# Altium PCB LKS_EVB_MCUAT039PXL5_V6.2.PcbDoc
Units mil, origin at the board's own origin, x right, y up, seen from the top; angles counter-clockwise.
Board outline 1544.1 x 1580 mil, 2 copper layers (Top Layer, Bottom Layer); 72 components, 49 nets, 196 pads, 133 vias.
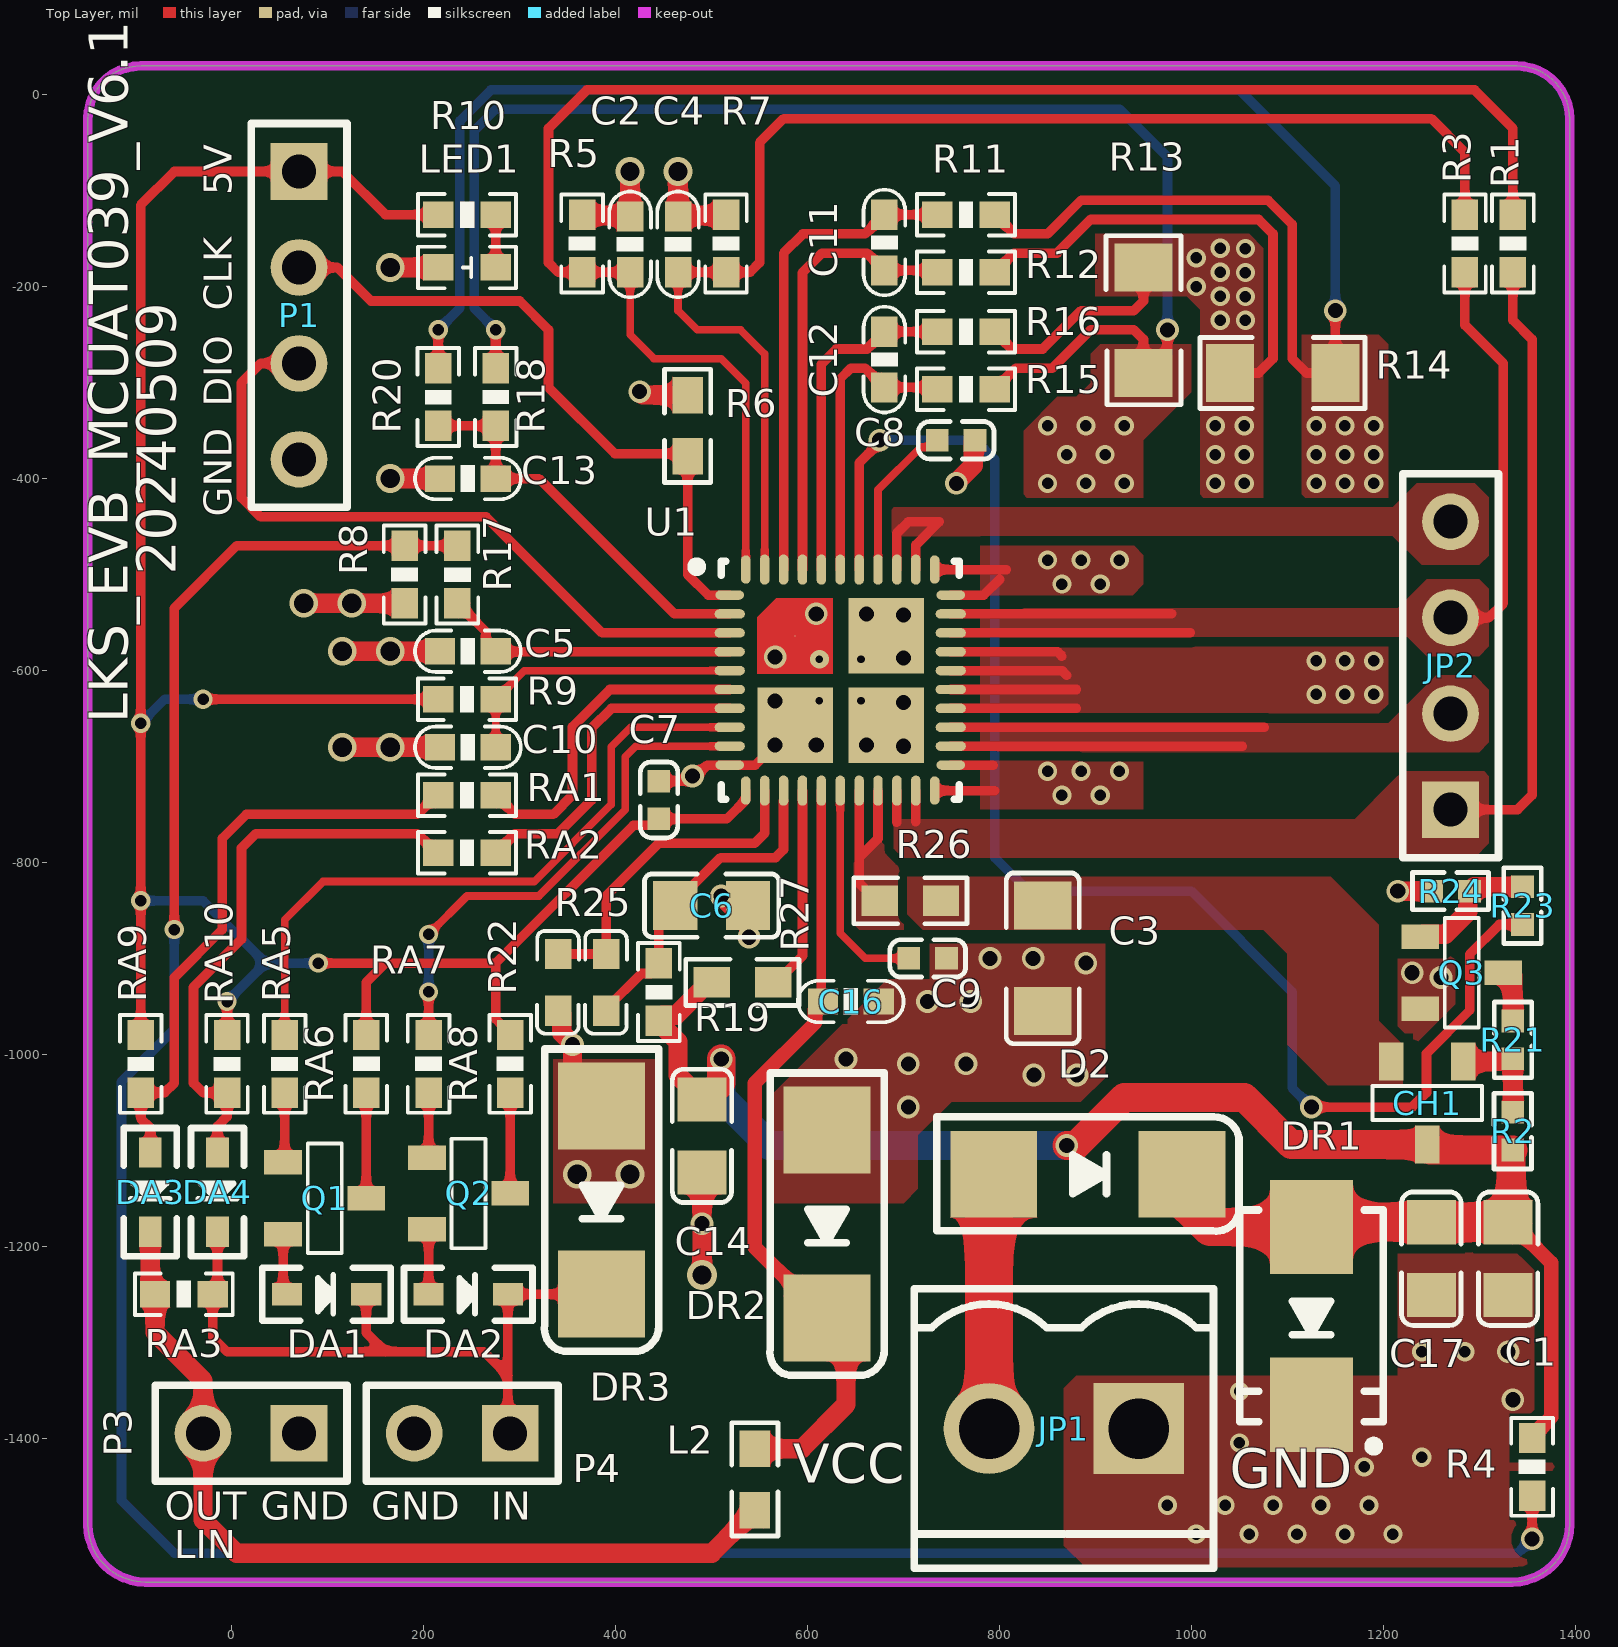
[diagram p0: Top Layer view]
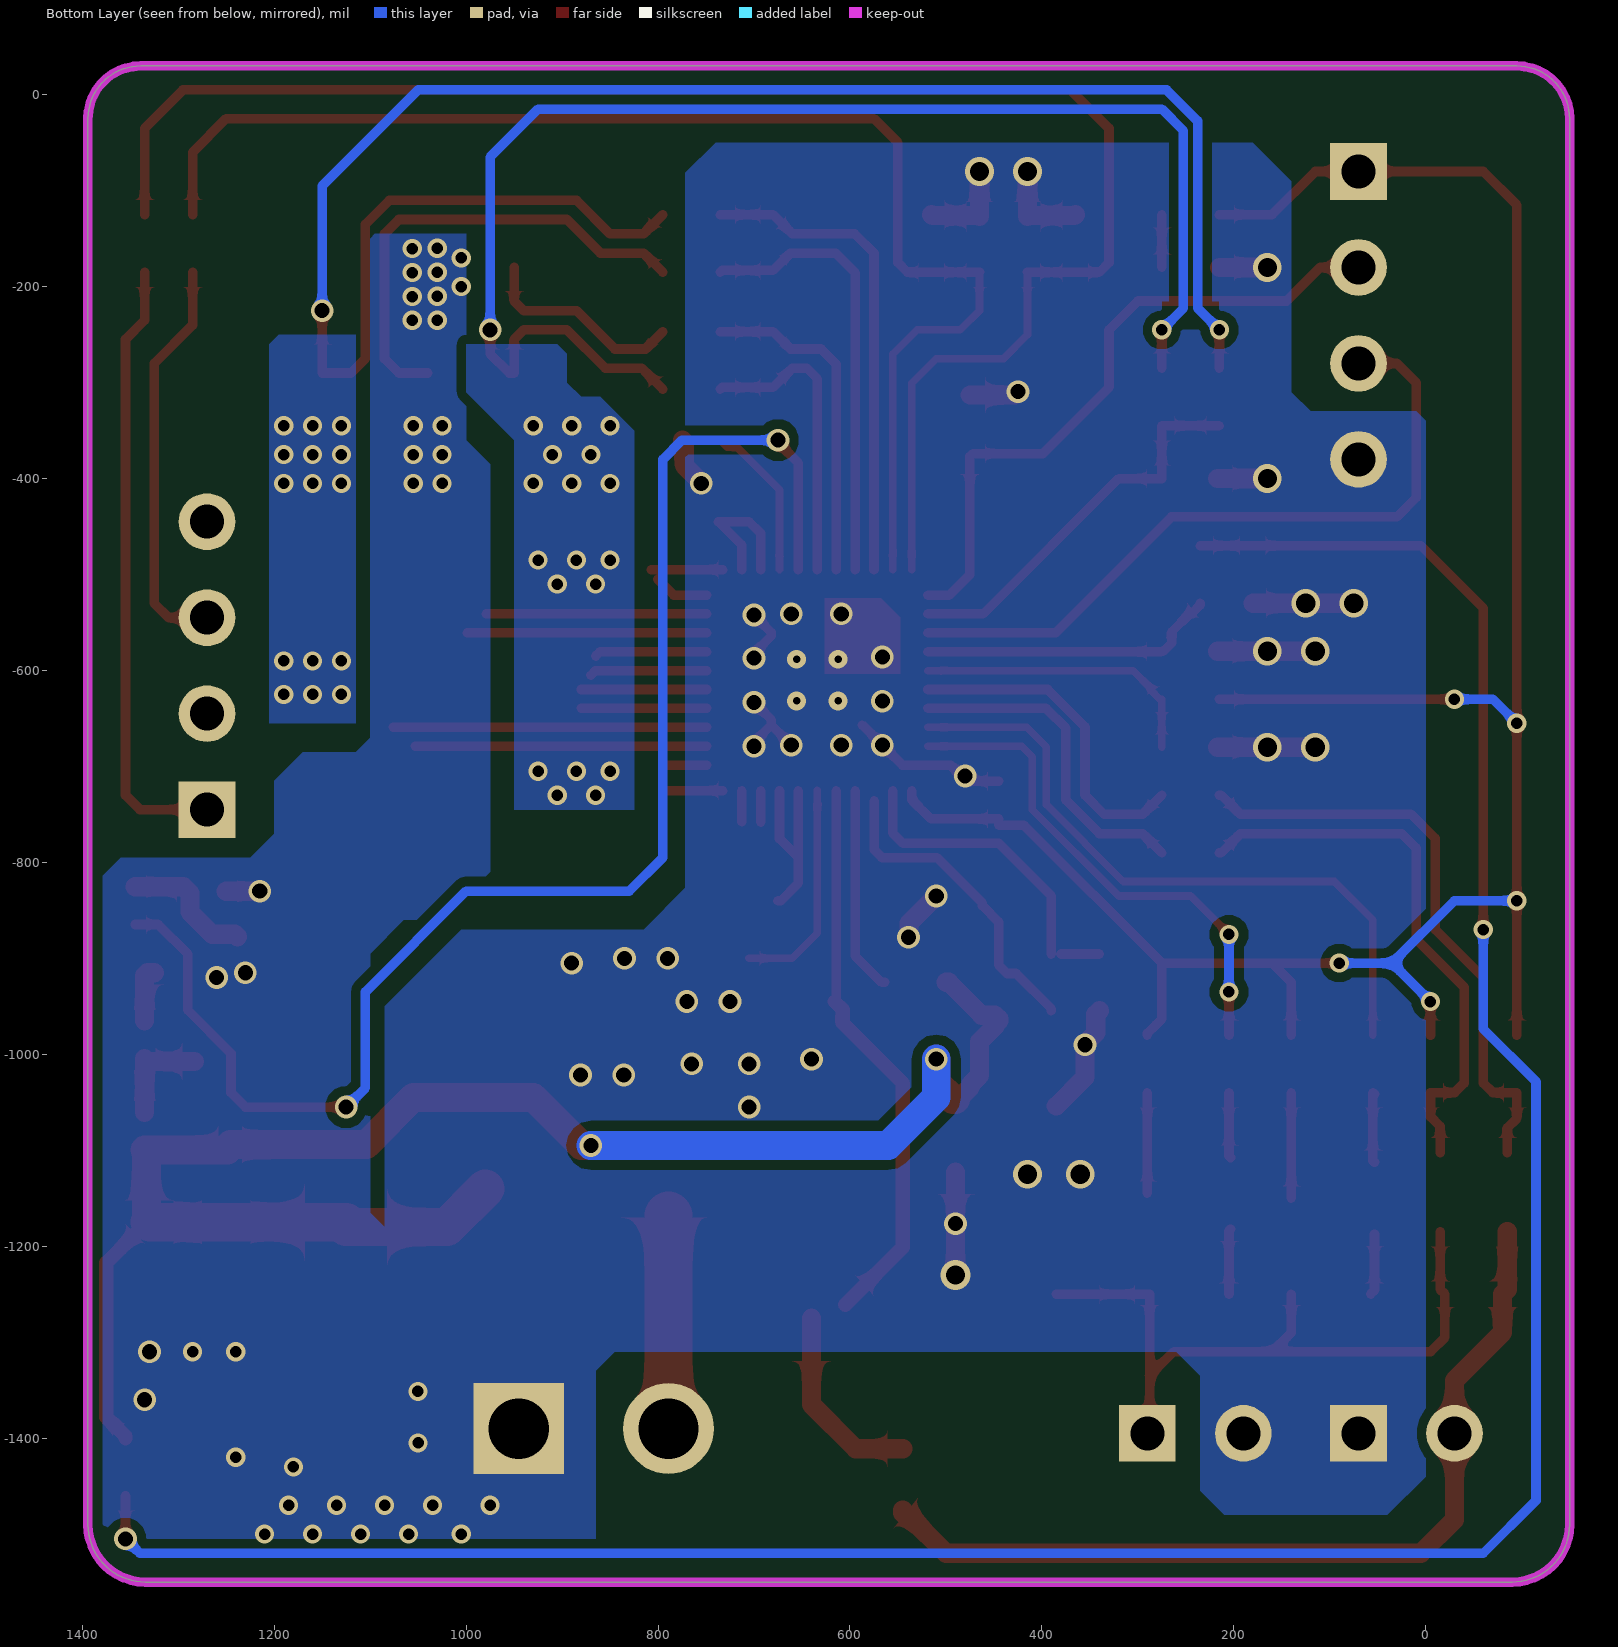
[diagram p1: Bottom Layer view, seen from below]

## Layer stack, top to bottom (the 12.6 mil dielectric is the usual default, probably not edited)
Top Solder: solder mask 0.4, Solder Resist, Dk 3.5
Top Layer: signal copper 1.4
Dielectric1: dielectric 12.6, FR-4, Dk 4.8
Bottom Layer: signal copper 1.4
Bottom Solder: solder mask 0.4, Solder Resist, Dk 3.5

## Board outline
-150,-1490 -150,-25 cw(c-95,-25) -95,30 1339.1,30 cw(c1339.1,-25) 1394.1,-25 1394.1,-1490 cw(c1334.1,-1490) 1334.1,-1550 -90,-1550 cw(c-90,-1490)

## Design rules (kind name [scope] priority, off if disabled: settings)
Clearance Clearance_1 [InPolygon] p1: gap=10 ignorepadtopadclearanceinfootprint=FALSE
Clearance [All] p2: gap=5 ignorepadtopadclearanceinfootprint=FALSE
ComponentClearance [All] p1: gap=0 collisioncheckmode=3 verticalgap=0 showdistances=FALSE
FabricationTestpoint [(IsPad And (OnTopLayer Or OnBottomLayer))] p1: side=3 testpointundercomponent=TRUE minsize=40 maxsize=100 preferedsize=60 minholesize=0 maxholesize=40 preferedholesize=32 testpointgrid=1 allowsidetop=TRUE allowsidebottom=TRUE usegrid=TRUE gridtolerance=0.01
HoleSize [All] p1: absolutevalues=TRUE maxlimit=100 minlimit=0 maxpercent=80.000 minpercent=20.000
PolygonConnect [All] p1: connectstyle=Direct reliefconductorwidth=30 reliefentries=4 polygonreliefangle="90 Angle" airgapwidth=10
RoutingVias [All] p1: holewidth=12 width=20 viastyle="Through Hole" minholewidth=0 minwidth=10 maxholewidth=100 maxwidth=200
SilkToSolderMaskClearance SilkscreenOverComponentPads [IsPad] p1: minsilkscreentomaskgap=10 clearancetoexposedcopper=TRUE
SolderMaskExpansion [All] p1: expansion=4 istentingtop=FALSE
Width [All] p1: maxlimit=100 minlimit=7.87 preferedwidth=10
26 further rules are at their usual default settings.

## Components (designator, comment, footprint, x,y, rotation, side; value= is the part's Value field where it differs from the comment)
C1 "100nF/50V" 0805C 1330,-1213 r270 top
C2 "1nF/50V" 0603C 415,-156 r90 top
C3 "CL31A226KAHNNNE" 1206C 845,-900 r270 top
C4 "1nF/50V" 0603C 465,-156 r90 top
C5 "100nF/50V" 0603C 246,-580 r180 top
C6 "2.2uF/50V" 0805C 500,-845 r0 top
C7 "CL05A105KO5NNNC" 0402C 445,-735 r90 top
C8 "CL05A105KO5NNNC" 0402C 754.68,-360 r0 top
C9 "CL05A105KO5NNNC" 0402C 725,-900 r0 top
C10 "100nF/50V" 0603C 246,-680 r180 top
C11 "100pF/50V" 0603C 680,-154 r270 top
C12 "100pF/50V" 0603C 680,-276 r90 top
C13 "1nF/50V" 0603C 246,-400 r180 top
C14 "10uF/50V" 0805C 490,-1085 r270 top
C16 "100pF/50V" 0603C 645,-945 r0 top
C17 "10uF/50V" 0805C 1250,-1213 r270 top
CH1 "PMV250EPEAR" SOT-23#1 1285,-1015 r180 top
D2 "SSL310" SMA 794,-1125 r0 top
DA1 "1N4007" SOD-323 98.66,-1250 r0 top
DA2 "1N4007" SOD-323 246.34,-1250 r0 top
DA3 "1N4007" SOD-323 -85,-1143.66 r270 top
DA4 "1N4007" SOD-323 -15,-1143.66 r270 top
DR1 "SMBJ33CA" SMB 1125,-1272.52 r270 top
DR2 "SMAJ48A" SMA 620,-1079 r270 top
DR3 "SMAJ48A" SMA 385,-1054 r270 top
JP1 "B2P-VH(LF)(SN)" HT3.96-LI-2P 867.05,-1390 r180 top
JP2 "HDR-1X4" "HDR 1X4" 1270,-745 r90 top
L2 "120R@100Mhz" 0603R#1 545,-1443 r90 top value=K
LED1 "LED" "LED 0603G" 245,-180 r180 top
P1 "HDR-1X4" "HDR 1X4" 70,-80 r270 top
P3 "1X2" "HDR 1X2" 70,-1395 r180 top
P4 "1X2" "HDR 1X2" 290,-1395 r180 top
Q1 "S8050" SOT-23#2 96.69,-1150 r270 top
Q2 "S8050" SOT-23#2 246.69,-1145 r270 top
Q3 "SS8050" SOT-23#1 1245.87,-875.83 r270 top
R1 "10K  1%" 0603R#2 1335,-155 r90 top value=K
R2 "51K 5%" 0402R 1335,-1080 r270 top value=K
R3 "10K  1%" 0603R#2 1285,-155 r90 top value=K
R4 "510K  1%" 0603R#2 1355,-1430 r270 top value=K
R5 "1K 1%" 0603R#2 365,-155 r90 top value=K
R6 "1K" 0603R#1 475,-345 r270 top value=K
R7 "1K 1%" 0603R#2 515,-155 r90 top value=K
R8 "30K 1%" 0603R#2 180,-500 r90 top value=K
R9 "20K" 0603R#2 245,-630 r0 top value=K
R10 "3.3K" 0603R#2 245,-125 r180 top value=330
R11 "1K 1%" 0603R#2 765,-125 r180 top value=K
R12 "1K 1%" 0603R#2 765,-185 r180 top value=K
R13 "100mR 1%" 1206R 950,-235 r270 top value=K
R14 "100mR 1%" 1206R 1095,-290 r0 top value=K
R15 "1K 1%" 0603R#2 765,-306.95 r180 top value=K
R16 "1K 1%" 0603R#2 765,-246.95 r180 top value=K
R17 "1K" 0603R#2 235,-500 r90 top value=K
R18 "2K 1%" 0603R#2 275,-315 r90 top value=K
R19 "51R" 0603R#2 445,-935 r90 top value=K
R20 "2K 1%" 0603R#2 215,-315 r90 top value=K
R21 "4.7K 5%" 0402R 1335,-985 r90 top value=K
R22 "10K" "0603C _1" 340,-925 r270 top value=K
R23 "1K 5%" 0402R 1345,-845 r270 top value=K
R24 "10K 5%" 0402R 1270,-830 r180 top value=K
R25 "NC" "0603C _1" 390,-925 r270 top value=K
R26 "0R" 0603R#1 707,-840 r0 top value=K
R27 "0R" 0603R#1 532,-925 r0 top value=K
RA1 "5K" 0603R#2 245,-730 r180 top
RA2 "5K" 0603R#2 245,-790 r180 top
RA3 "1.5R" 0603R#2 -50,-1250 r0 top
RA5 "10K" 0603R#2 55,-1010 r90 top
RA6 "3.9K" 0603R#2 140,-1010 r270 top
RA7 "10K" 0603R#2 205,-1010 r90 top
RA8 "1.3K" 0603R#2 290,-1010 r270 top
RA9 "100K" 0603R#2 -95,-1010 r90 top
RA10 "100K" 0603R#2 -5,-1010 r90 top
U1 "LKS32AT039PXL5G6Q9" QFN42-AT039PXL5 634,-610 r0 top

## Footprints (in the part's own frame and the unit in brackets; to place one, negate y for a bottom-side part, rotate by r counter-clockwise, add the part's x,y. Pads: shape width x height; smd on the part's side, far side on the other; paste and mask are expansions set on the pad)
0402C [mm]
  rect 0.6x0.6 smd: 1(-0.5,0) 2(0.5,0)
  silkscreen extent -1,-0.5 1,0.49, body extent -0.5,-0.25 0.5,0.25, height 0.35
0402R [mm]
  rect 0.6x0.6 smd: 1(-0.5,0) 2(0.5,0)
  silkscreen extent -1,-0.5 1,0.49, body extent -0.5,-0.25 0.5,0.25, height 0.35
0603C [mm] "电容"
  rect 0.8x0.7 smd: 1(-0.737,0) 2(0.738,0)
  silkscreen extent -1.4,-0.55 1.4,0.55, body extent -0.8,-0.41 0.8,0.41, height 0.81
"0603C _1" [mm]
  rect 0.8x0.7 smd: 1(-0.75,0) 2(0.75,0)
  silkscreen extent -1.36,-0.56 1.36,0.55, body extent -0.8,-0.41 0.8,0.41, height 0.81
0603R#1 [mil]
  rect 38x32 smd: 1(-32,0) 2(32,0)
  silkscreen extent -59,-24 59,24, body extent -31,-16 32,16, height 16
0603R#2 [mil] "电阻"
  rect 31.5x27.56 smd: 1(-30,0) 2(30,0)
  silkscreen extent -51,-22 51,22, body extent -31,-16 32,16, height 18
0805C [mil] "电容"
  rect 46x51.18 smd: 1(-38,0) 2(38,0)
  silkscreen extent -69,-31 70,31, body extent -39,-24 39,24, height 20
1206C [mil]
  rect 50x60 smd: 1(-55,0) 2(55,0)
  silkscreen extent -89,-38 89,38, body extent -61,-31 65,32, height 24
1206R [mil]
  rect 50x60 smd: 1(-55,0) 2(55,0)
  silkscreen extent -88,-39 88,39, body extent -62,-31 64,32, height 24
"HDR 1X2" [mm] "单排针 2.54mm"
  rect 1.5x1.5 hole 0.9: 1(0,0)
  round 1.5 hole 0.9: 2(2.54,0)
  silkscreen extent -1.27,-1.27 3.81,1.27, body extent -1.27,-1.27 3.81,1.27, height 8.5
"HDR 1X4" [mm] "单排针 2.54mm"
  rect 1.5x1.5 hole 0.9: 1(0,0)
  round 1.5 hole 0.9: 2(2.54,0) 3(5.08,0) 4(7.62,0)
  silkscreen extent -1.27,-1.27 8.89,1.27, body extent -1.27,-1.27 8.89,1.27, height 8.5
HT3.96-LI-2P [mm] "HT3.96立插端子"
  rect 2.4x2.4 hole 1.6: 1(-1.98,0)
  round 2.4 hole 1.6: 2(1.98,0)
  silkscreen extent -3.96,-3.7 3.96,3.7, body extent -3.98,-3.7 3.98,3.7, height 10.05
"LED 0603G" [mm] "LED"
  rect 0.8x0.7 smd: 1(-0.762,0) 2(0.762,0)
  silkscreen extent -1.3,-0.55 1.3,0.55, body extent -0.8,-0.4 0.8,0.4, height 0.47
QFN42-AT039PXL5 [mm] "QFN, 42-Leads, Body 6.00x6.00mm, Pitch 0.50mm, Thermal Pad 2.00x2.00mm, IPC Medium Density"
  rect 2x2 smd: 0(-1.194,-1.194) 0(1.219,-1.194) 0(1.219,1.168)
  round 0.025 smd: 0(-1.194,1.168)
  oval 0.75x0.25 smd: 1(-2.925,2.25) 10(-2.925,-2.25) 22(2.925,-2.25) 31(2.925,2.25)
  oval 0.8x0.25 smd: 2(-2.925,1.75) 3(-2.925,1.25) 4(-2.925,0.75) 5(-2.925,0.25) 6(-2.925,-0.25) 7(-2.925,-0.75) 8(-2.925,-1.25) 9(-2.925,-1.75) 23(2.925,-1.75) 24(2.925,-1.25) 25(2.925,-0.75) 26(2.925,-0.25) 27(2.925,0.25) 28(2.925,0.75) 29(2.925,1.25) 30(2.925,1.75)
  oval 0.25x0.75 smd: 11(-2.5,-2.925) 21(2.5,-2.925) 32(2.5,2.925) 42(-2.5,2.925)
  oval 0.25x0.8 smd: 12(-2,-2.925) 13(-1.5,-2.925) 14(-1,-2.925) 15(-0.5,-2.925) 16(0,-2.925) 17(0.5,-2.925) 18(1,-2.925) 19(1.5,-2.925) 20(2,-2.925) 33(2,2.925) 34(1.5,2.925) 35(1,2.925) 36(0.5,2.925) 37(0,2.925) 38(-0.5,2.925) 39(-1,2.925) 40(-1.5,2.925) 41(-2,2.925)
  Top Layer region: -2.194,0.168 -2.194,1.668 -1.694,2.168 -0.194,2.168 -0.194,0.168
  silkscreen extent -3.92,-3.15 3.15,3.15, body extent -3,-2.95 3,3.05, height 0.55
SMA [mm] "二极管  4.5x2.6x2.2mm"
  rect 2.3x2.3 smd: 1(0,0) 2(4.978,0)
  silkscreen extent -1.51,-1.51 6.49,1.52, body extent -0.06,-1.3 5.04,1.3, height 2.15
SMB [mm] "4.7*3.9*2.2mm(长宽高，不包括引脚）"
  rect 2.5x2.2 smd: 1(-2.35,0) 2(2.35,0)
  silkscreen extent -2.8,-1.9 3.57,1.9, body extent -2.63,-1.8 2.67,1.8, height 2.35
SOD-323 [mm] "二极管"
  rect 0.8x0.6 smd: 1(-1.05,0) 2(1.05,0)
  silkscreen extent -1.7,-0.7 1.7,0.7, body extent -1.34,-0.63 1.31,0.67, height 1
SOT-23#1 [mm]
  rect 0.65x1 smd: 1(0.045,-0.19) 2(1.945,-0.19) 3(0.995,2.01)
  silkscreen extent -0.45,0.46 2.45,1.36
SOT-23#2 [mm]
  rect 0.65x1 smd: 1(-0.95,-1.1) 2(0.95,-1.1) 3(0,1.1)
  silkscreen extent -1.45,-0.45 1.45,0.45, body extent -1.5,-1.2 1.5,1.2, height 1.05

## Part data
C1 C6 C14 C16 C17: library part Capacitor, "Capacitor --贴片电容"
C2 C4 C5 C7 C8 C9 C11 C12 C13: library part CAP, "Capacitor"
C3: library part CAP, "Capacitor / 22uF/25V / 三星"
C10: library part C, "Capacitor"
CH1: library part P-MOS
D2: library part 1N4148, "高速开关二极管"
DA1 DA2 DA3 DA4: library part Diode, "Default Diode", PackageDocument=Sep-1996
DR1: library part DR, "瞬态电压抑制二极管   极性：双向 反向截止电压(Vrwm)：24V 击穿电压：26.7V 反向漏电流(Ir)：1uA 峰值脉冲电流(Ipp)@10/1000μs：15.5A 最大钳位电压：38.9V TVS瞬态抑制二极管@10/1000μs：11.3A 最大钳位电压：53.3V"
DR2 DR3: library part M_ZENER3, "Zener Diode"
JP1: library part "Header 2", "2P接插件"
JP2: library part "Header 4", "4P接插件"
L2 R1 R2 R3 R4 R5 R6 R7 R8 R9 R10 R11 R12 R15 R16 R17 R18 R19 R20 R21 R22 R23 R24 R25 R26 R27: library part Res, "Resistor"
LED1: "LED_Light"
P1: library part "Header 4", "Header, 4-Pin"
P3 P4: "接口"
Q1 Q2: library part NPN, "三极管"
Q3: library part NPN, "NPN Bipolar Transistor"
R13 R14: library part Res, "合金电阻Resistor"
RA1 RA2 RA3 RA5 RA6 RA7 RA8 RA9 RA10: library part Res2, "Resistor"
U1: "车规芯片 03x"

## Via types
v1: diameter 20, hole 12, Top Layer to Bottom Layer, 75 vias
v2: diameter 23.62, hole 15.75, Top Layer to Bottom Layer, 41 vias
v3: diameter 30, hole 20, Top Layer to Bottom Layer, 12 vias
v4: diameter 19.68, hole 7.87, Top Layer to Bottom Layer, 4 vias
v5: diameter 31.5, hole 19.68, Top Layer to Bottom Layer, 1 vias

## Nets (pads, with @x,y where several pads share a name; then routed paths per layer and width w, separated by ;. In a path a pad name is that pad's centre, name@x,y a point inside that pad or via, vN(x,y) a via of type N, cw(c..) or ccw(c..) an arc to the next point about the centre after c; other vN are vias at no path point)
+5V: C7.1 P1.1 R9.1 R10.2 RA6.1 RA8.1 RA9.2 RA10.2 U1.11 | length 2519.9
  Top Layer w10: RA9.2 v1(-95,-840) v1(-95,-655) -95,-115 -60,-80 P1.1 115,-80 160,-125 R10.2 ; v1(-30,-630) R9.1 ; RA10.2 v1(-5,-945) ; v1(90,-905) 160,-905 ; RA6.1 140,-925 160,-905 ; RA8.1 290,-978.03 281.22,-969.25 280.86,-969.25 275,-963.39 275,-905 ; C7.1@445,-760.89 444.39,-761.5 418.5,-761.5 275,-905 ; C7.1 515.73,-754.68 535.57,-734.84 U1.11 ; 160,-905 275,-905
  Bottom Layer w10: v1(-95,-840) -30,-840 35,-905 ; v1(-95,-655) -70,-630 v1(-30,-630) ; v1(-5,-945) 35,-905 ; v1(90,-905) 35,-905
control1: RA5.2 U1.8 | length 702.2
  Top Layer w8: RA5.2 55,-860 95,-820 315,-820 395.39,-739.61 395.39,-679.61 415.79,-659.21 U1.8
control2: RA7.2 U1.9 | length 532.3
  Top Layer w8: v1(205,-875) 245,-835 320,-835 410,-745 410,-690 421.1,-678.9 U1.9
  Top Layer w10: RA7.2 v1(205,-935)
  Bottom Layer w10: v1(205,-935) v1(205,-875)
GND: C1.2 C2.2 C3.2 C4.2 C5.2 C6.2 C7.2 C8.2 C9.2 C10.2 C13.2 C14.2 C16.2 C17.2 DR1.2 DR2.1 DR3.1 JP1.1 LED1.2 P1.4 P3.1 P4.2 Q3.2 R5.2 R6.1 R7.2 R8.1 R12.1 R13.1 R14.1 R16.1 R22.2 R24.2 U1.0 U1.10 | length 2060.7
  Top Layer w10: C7.2 478.46,-715.31 478.46,-715.22 486.29,-707.39 486.39,-707.39 495.2,-698.58 U1.10 545.42,-698.58 v2(566.21,-677.79) U1.0@587,-657 ; v2(661.21,-677.79) U1.0@682,-657 ; v2(700,-679) 700,-675 U1.0@682,-657 ; v2(700,-633.21) 682,-651.21 U1.0@682,-657 ; v2(700,-587.21) 700,-582 682,-564 682,-560.21 v2(700,-542.21) ; R16.1 813.05,-265 845,-265 885,-225 940,-225 950,-215 R13.1 ; R12.1 815,-165 860,-165 895,-130 1070,-130 1085,-145 1085,-275 1070,-290 R14.1
  Top Layer w20: v3(75,-530) v3(125,-530) R8.1 ; v3(115,-680) v3(165,-680) C10.2 ; v3(115,-580) v3(165,-580) C5.2 ; v3(165,-400) C13.2 ; v3(165,-180) LED1.2 ; R22.2 343.78,-958.31 343.78,-977.8 355,-989.02 v2(355,-990) 355,-1024 DR3.1 ; R5.2 365.97,-125.97 414.03,-125.97 C2.2 v3(415,-80) ; v2@425,-310 428,-313 R6.1 ; v3(465,-80) C4.2 465.97,-125.97 514.03,-125.97 R7.2 ; v5(490,-1230) v2(490,-1176.5) C14.2 ; v2(510,-835) 538.5,-863.5 538.5,-877.5 v2(539,-878) ; v2(755,-405) 755,-404.02 772.56,-386.46 772.56,-361.81 C8.2 ; v2(1215,-830) R24.2
  other v1: 1005,-1500 1060,-1500 1110,-1500 1160,-1500 1210,-1500 975,-1470 1035,-1470 1085,-1470 1135,-1470 1185,-1470 1180,-1430 1240,-1420 1050,-1405 1050.2,-1351.26 1240,-1310 1285,-1310 1025,-405 1055,-405 1025,-375 1055,-375 1025,-345 1055,-345 1030,-235 1056.2,-235 1030,-210 1056.2,-210.32 1005,-200 1030,-185 1056.2,-185.32 1005,-170 1030,-160 1056.2,-160.32
  other v2: 1335,-1360 1330,-1310 705,-1055 835.73,-1021.57 880.73,-1021.57 705,-1010 765,-1010 640,-1005 725,-945 770,-945 1260,-920 1230,-915 890,-905 790,-900 835,-900 480,-710 609,-677.79 566.21,-632 566.21,-586 609,-541 661.21,-541 424.9,-309.39
  other v3: 360,-1125 415,-1125
  other v4: 612.35,-631.65 655.65,-631.65 612.35,-588.35 655.65,-588.35
LIN: DA3.2 L2.1 P3.2 RA3.1 | length 932.7
  Top Layer w20: DA3.2 -85,-1245 RA3.1 -80,-1290 -30,-1340 P3.2 -30,-1485 5,-1520 500,-1520 536,-1484 539,-1484 545,-1478 L2.1
LIN1: C16.1 DR2.2 L2.2 U1.15 | length 794.2
  Top Layer w10: C16.1@614.32,-945 U1.15
  Top Layer w15: DR2.2@605,-1261 545,-1201 545,-1030 607.63,-967.37 607.63,-953.37 C16.1
  Top Layer w20: L2.2 594,-1411 640,-1365 DR2.2@640,-1275
NetC8_1: C8.1 U1.35 | length 166.2
  Top Layer w8: U1.35 673.37,-411.63 717.7,-367.3 727.7,-367.3 C8.1
NetC9_1: C9.1 U1.16 | length 230.9
  Top Layer w8: U1.16 634,-874 660,-900 C9.1
NetCH1_1: CH1.1 R2.1 R21.1 | length 108.6
  Top Layer w20: CH1.1 1332.16,-1007.52 R21.1 R2.1
NetD2_1: D2.1 JP1.2 | length 222.2
  Top Layer w50: JP1.2 D2.1@789.09,-1167.84
NetDA1_1: DA1.1 Q1.2 | length 64.2
  Top Layer w10: Q1.2 53.39,-1246.06 DA1.1
NetDA1_2: DA1.2 DA2.2 DA4.2 DR3.2 P4.1 RA3.2 | length 747.9
  Top Layer w10: DA4.2 -15,-1245 RA3.2 -20,-1295 -5,-1310 160,-1310 ; DA1.2 140,-1290 160,-1310 ; P4.1@287.68,-1392.68 287.68,-1335 ; DR3.2 DA2.2 287.68,-1335 ; 160,-1310 262.68,-1310 287.68,-1335
  Top Layer w20: P4.1@287.68,-1392.68 P4.1
NetDA2_1: DA2.1 Q2.2 | length 68.3
  Top Layer w10: Q2.2 205,-1184.01 DA2.1
NetDA3_1: DA3.1 RA1.2 RA9.1 | length 625
  Top Layer w10: DA3.1 -85,-1076.73 -95,-1066.73 RA9.1 -70,-1040 -60,-1030 -60,-920 -10,-870 -10,-775 15,-750 193.03,-750 213.03,-730 RA1.2
NetDA4_1: DA4.1 RA2.2 RA10.1 | length 590.8
  Top Layer w10: DA4.1 -15,-1075 -5,-1065 RA10.1 -30,-1040 -40,-1030 -40,-930 10,-880 10,-785 25,-770 193.03,-770 213.03,-790 RA2.2
NetLED1_1: LED1.1 R10.1 | length 55
  Top Layer w10: LED1.1 R10.1
NetQ1_1: Q1.1 RA5.1 | length 75.5
  Top Layer w10: Q1.1 55,-1110.98 RA5.1 RA5.1@53.39,-1041.61
NetQ1_3: Q1.3 RA6.2 | length 110
  Top Layer w10: Q1.3 RA6.2
NetQ2_1: Q2.1 RA7.1 | length 68.3
  Top Layer w10: Q2.1 205,-1105.98 RA7.1
NetQ2_3: Q2.3 RA8.2 | length 105
  Top Layer w10: Q2.3 RA8.2
NetQ3_1: Q3.1 R23.1 R24.1 | length 139.9
  Top Layer w20: Q3.1 1241.18,-874.8 1264.8,-874.8 1287.87,-851.73 1287.87,-831.81 1294.37,-825.32 R23.1
NetQ3_3: Q3.3 R21.2 | length 58.5
  Top Layer w20: Q3.3 1331.89,-915 1335,-918.11 R21.2
NetR4_2: R4.2 R8.2 R17.2 | length 2818.7
  Top Layer w10: v1(-60,-870) -60,-535 5,-470 R8.2 R17.2 ; v2(1355,-1505) R4.2
  Bottom Layer w10: v1(-60,-870) -60,-973.5 -115,-1028.5 -115,-1465 -60,-1520 1340,-1520 v2(1355,-1505)
NetR22_1: R22.1 R25.1 U1.12 | length 337.3
  Top Layer w10: R22.1 R25.1@380,-895.47 ; R25.1 390,-835 445,-780 545,-780 555.26,-769.74 U1.12
NetR26_1: R26.1 U1.17 U1.18 | length 203.4
  Top Layer w10: U1.17 653.69,-795 ; U1.18 673.37,-775.31 653.69,-795 ; R26.1 672,-840 653.69,-821.69 653.69,-795
NetR27_2: R27.2 U1.14 | length 214.3
  Top Layer w10: R27.2 567,-925 594.63,-897.37 U1.14
NRST: C10.1 R9.2 U1.5 | length 307.4
  Top Layer w8: C10.1 R9.2 276.97,-630 286.75,-620.22 286.75,-618.25 304.84,-600.16 U1.5
OC: C13.1 R18.1 R20.1 U1.2 | length 417.3
  Top Layer w10: R20.1 R18.1 C13.1 320,-400 461.1,-541.1 U1.2
OPA0_IN: C11.2 R12.2 U1.39 | length 466.6
  Top Layer w10: U1.39 594.63,-185.37 615,-165 661.95,-165 C11.2 733.05,-183.05 R12.2
OPA0_IN_B: RA2.1 U1.7 | length 350.1
  Top Layer w10: RA2.1 295,-770 340,-770 375,-735 375,-660 395.47,-639.53 U1.7
OPA0_IP: C11.1 R11.2 U1.40 | length 506.4
  Top Layer w10: U1.40 574.95,-165.05 595,-145 660,-145 C11.1 R11.2
OPA0_IP_B: RA1.1 U1.6 | length 347.8
  Top Layer w10: RA1.1 295,-750 335,-750 355,-730 355,-658.79 393.94,-619.84 U1.6
OPA1_IN: C12.2 R16.2 U1.38 | length 348.8
  Top Layer w10: U1.38 614.32,-280.68 630,-265 661.95,-265 C12.2 R16.2
OPA1_IP: C12.1 R15.2 U1.37 | length 313.5
  Top Layer w10: U1.37 634,-296 645,-285 660,-285 C12.1 733.05,-305 R15.2
OUT0_0: JP2.1 R1.1 U1.19 U1.20 | length 710.1
  Top Layer w10: 693.06,-758.06 U1.19 ; 712.74,-757.74 U1.20 U1.20@712.82,-725.24 ; JP2.1 1340,-745 1355,-730 1355,-255 1335,-235 R1.1
OUT0_1: JP2.4 U1.33 U1.34 | length 146.7
  Top Layer w10: U1.34 693.06,-456.94 705,-445 736.99,-445 712.74,-469.25 U1.33
OUT0_2: JP2.3 R3.1 U1.29 U1.30 | length 902.5
  Top Layer w10: U1.29 998.86,-560.79 ; U1.30 979.17,-541.1 ; JP2.3 1310,-545 1325,-530 1325,-280 1285,-240 R3.1
OUT0_3: JP2.2 U1.23 U1.24 | length 630.5
  Top Layer w10: U1.23 1052.8,-678.9 ; U1.24 1076,-659.21
P0: C2.1 R1.2 R5.1 U1.42 | length 1758.1
  Top Layer w8: C2.1 415,-250 440,-275 510,-275 535.57,-300.57 U1.42
  Top Layer w10: C2.1 R5.1 340,-185 330,-175 330,-35 370,5 1295,5 1335,-35 R1.2
P2: C4.1 R3.2 R7.1 U1.41 | length 1412.6
  Top Layer w8: C4.1 465,-225 485,-245 530,-245 555.26,-270.26 U1.41
  Top Layer w10: C4.1 R7.1 540,-185 550,-175 550,-50 575,-25 1250,-25 1285,-60 R3.2
PGND0: R13.2 R15.1 R18.2 U1.21 U1.22 U1.31 U1.32 | length 1709.2
  Top Layer w10: R18.2 v1(275,-245) ; U1.21 795,-725.16 ; U1.32 732.5,-494.92 806.92,-494.92 ; U1.22 793.58,-698.58 ; U1.31 783.58,-521.42 800,-505 ; R15.1 816.95,-285 855,-285 895,-245 940,-245 950,-255 R13.2 955,-290 975,-270 v2(975,-245) ; v1@862.29,-510 v1(865,-510)
  Bottom Layer w10: v1(275,-245) 252.64,-222.64 252.64,-37.36 275,-15 925,-15 975,-65 v2(975,-245)
  other v1: 865,-730 905,-730 850,-705 885,-705 925,-705 905,-510 850,-485 885,-485 925,-485 850,-405 890,-405 930,-405 870,-375 910,-375 850,-345 890,-345 930,-345
PGND1: R11.1 R14.2 R20.2 U1.25 U1.26 U1.27 U1.28 | length 2465.8
  Top Layer w10: R20.2 v1(215,-245) ; U1.25 880,-639.53 ; U1.26 880,-619.84 ; U1.27 865.16,-600.16 870,-605 ; U1.28 860.47,-580.47 865,-585 ; R11.1 815,-145 850,-145 885,-110 1080,-110 1105,-135 1105,-275 1120,-290 R14.2 v2(1150,-225)
  Bottom Layer w10: v1(215,-245) 237.64,-222.36 237.64,-27.36 270,5 1050,5 1150,-95 v2(1150,-225)
  other v1: 1130,-625 1160,-625 1190,-625 1130,-590 1160,-590 1190,-590 1130,-405 1160,-405 1190,-405 1130,-375 1160,-375 1190,-375 1130,-345 1160,-345 1190,-345
PVDD_EN: R23.2 U1.36 | length 1540.3
  Top Layer w10: U1.36 653.69,-383.67 675,-362.36 v2(675,-360) ; v2(1125,-1055) 1230,-1055 1245,-1040 1245,-999.13 1290,-954.13 1290,-895.57 1320.88,-864.69 R23.2
  Bottom Layer w10: v2(675,-360) 775,-360 795,-380 795,-795 830,-830 1000,-830 1105,-935 1105,-1035 v2(1125,-1055)
SWCLK: P1.2 R6.2 U1.1 | length 697.5
  Top Layer w10: P1.2 110,-180 145,-215 300,-215 330,-245 330,-305 399,-374 472,-374 R6.2 475,-500 496.42,-521.42 U1.1
SWDIO: P1.3 U1.3 | length 755.4
  Top Layer w10: P1.3 30,-280 10,-300 10,-420 30,-440 265,-440 385.79,-560.79 U1.3
Vbat: C3.1 CH1.2 R26.2
VIN: C6.1 R19.2 R25.2 U1.13 | length 334.2
  Top Layer w10: R25.2 390,-952.56 426.81,-915.75 436.22,-915.75 445,-906.97 R19.2 445,-862 C6.1 462,-842.41 509.41,-795 566.59,-795 574.87,-786.72 U1.13@574.87,-735.91
VIN/VBAT: C1.1 C14.1 C17.1 CH1.3 D2.2 DR1.1 R2.2 R4.1 R19.1 R27.1 | length 1854.8
  Top Layer w15: C1.1 1332.59,-1175 1375,-1217.41 1375,-1378.03 1355,-1398.03 R4.1
  Top Layer w20: C14.1 487.41,-1047 474.41,-1034 474.41,-1031.41 465,-1022 465,-986.97 448.78,-970.75 448.78,-968.78 R19.1 445,-963.03 448.78,-959.25 462.75,-959.25 497,-925 R27.1
  Top Layer w30: C14.1 492.59,-1047 510,-1029.59 v2(510,-1005) ; v2(870,-1095) 880,-1095 930,-1045 1055,-1045 1104.13,-1094.13 CH1.3 1245.83,-1096.89 1248.62,-1099.69 R2.2 1333.19,-1101.5 1333.19,-1171.81 C1.1
  Top Layer w40: D2.2@980,-1140 1020,-1180 DR1.1 ; DR1.1@1125,-1175 C17.1 C1.1
  Bottom Layer w30: v2(510,-1005) 510,-1045 560,-1095 v2(870,-1095)
VOL_ADC: C5.1 R17.1 U1.4 | length 312.7
  Top Layer w10: R17.1 235,-531.97 243.78,-540.75 245.75,-540.75 264.63,-559.63 264.63,-571.22 273.41,-580 C5.1 275.47,-580.47 U1.4

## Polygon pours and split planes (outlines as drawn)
NetR26_1 on Top Layer "NONET_L-01_P-001" (solid, remove dead copper, pour order 59): 673.37,-775.31 648,-800.69 648,-864 654,-870 700,-870 700,-801.94
Vbat on Top Layer "10" (solid, remove dead copper, pour order 22): 1100,-895 1100,-990 1142.2,-1032.2 1220,-1032.2 1220,-990 1195,-965 1195,-865 1145,-815 700,-815 700,-850 720,-870 1075,-870
GND on Top Layer "NONET_L-01_P-001" (solid, remove dead copper, pour order 58): 700,-1155 715,-1140 715,-1084.5 749.48,-1050.03 884.7,-1049.7 910,-1024.4 910,-885 682.66,-885 682.66,-922.34 555,-1050 555,-1155
GND on Top Layer "10" (solid, remove dead copper, pour order 35): 1215,-855 1215,-1335 880,-1335 867.05,-1347.95 867.05,-1512.05 905,-1550 1355,-1550 1395,-1510 1395,-865 1385,-855
OUT0_1 on Top Layer "NONET_L-01_P-001" (solid, remove dead copper, pour order 18): 685,-435 690,-430 1210,-430 1235,-405 1295,-405 1315,-425 1315,-475 1300,-490 1240,-490 1210,-460 690,-460 685,-455
GND on Top Layer "10" (solid, remove dead copper, pour order 53): 900,-145 1060,-145 1075,-160 1075,-420 1009,-420 1009,-224 995,-210 900,-210
PGND1 on Top Layer "10" (solid, remove dead copper, pour order 52): 1115,-250 1115,-430 1205,-430 1205,-260 1195,-250
PGND0 on Top Layer "10" (solid, remove dead copper, pour order 45): 905,-260 895,-270 895,-300 880,-315 860,-315 825,-350 825,-425 950,-425 950,-360 1000,-310 1000,-260
PGND1 on Top Layer "10" (solid, remove dead copper, pour order 23): 780,-575 1205,-575 1205,-635 1195,-645 780,-645
GND on Top Layer "10" (solid, remove dead copper, pour order 44): 445,-1005 335,-1005 335,-1155 445,-1155
PGND0 on Top Layer "10" (solid, remove dead copper, pour order 29): 780,-690 780,-745 950,-745 950,-690
PGND0 on Top Layer "10" (solid, remove dead copper, pour order 28): 780,-469.25 780,-521.42 938.58,-521.42 950,-510 950,-480 939.25,-469.25
OUT0_2 on Top Layer "NONET_L-01_P-001" (solid, remove dead copper, pour order 19): 780,-535 780,-565 1225,-565 1245,-585 1300,-585 1310,-575 1310,-515 1300,-505 1245,-505 1215,-535
OUT0_0 on Top Layer "10" (solid, remove dead copper, pour order 21): 685,-755 1170,-755 1210,-715 1220,-705 1305,-705 1310,-710 1310,-780 1295,-795 699.09,-795 685,-780.92
OUT0_3 on Top Layer "NONET_L-01_P-001" (solid, remove dead copper, pour order 20): 780,-655 780,-685 1300,-685 1310,-675 1310,-620 1295,-605 1255,-605 1205,-655
GND on Bottom Layer "10" (solid, remove dead copper, pour order 56): 740,-50 180,-50 140,-90 140,-310 120,-330 10,-330 0,-340 0,-1440 40,-1480 210,-1480 235,-1455 235,-1335 260,-1310 845,-1310 867.05,-1332.05 867.05,-1522.05 880,-1535 1055,-1535 1085,-1505 1085,-950 1005,-870 815,-870 771.37,-826.37 771.37,-383.63 771.37,-81.37
GND on Bottom Layer "10" (solid, remove dead copper, pour order 55): 1000,-145 1000,-360 975,-385 975,-810 1025,-860 1065,-860 1100,-895 1100,-1165 1050,-1215 896.38,-1215 865,-1246.38 865,-1520 880,-1535 1365,-1535 1380,-1520 1380,-815 1360,-795 1225,-795 1200,-770 1200,-715 1170,-685 1115,-685 1100,-670 1100,-150 1095,-145
PGND1 on Bottom Layer "10" (solid, remove dead copper, pour order 51): 1115,-250 1115,-655 1205,-655 1205,-260 1195,-250
PGND0 on Bottom Layer "10" (solid, remove dead copper, pour order 27): 860,-315 825,-350 825,-745 950,-745 950,-360 1000,-310 1000,-260 905,-260 895,-270 895,-300 880,-315
GND on Top Component Center "10" (solid, remove dead copper, pour order 41): 180,-50 140,-90 140,-310 120,-330 10,-330 0,-340 0,-1410 70,-1480 210,-1480 235,-1455 235,-1335 260,-1310 395,-1310 413.94,-1291.06 856.06,-1291.06 865,-1300 865,-1525 1148.77,-1525 1178.77,-1495 1180,-1495 1180,-1220 1215,-1185 1215,-385 1165,-385 1142.5,-407.5 1142.5,-782.5 1120,-805 1015,-805 975,-765 789,-765 765,-741 765,-390 816,-339 816,-71 795,-50

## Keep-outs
Keep-Out Layer:
  the board outline again, w10

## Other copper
Bottom Layer:
  pour cut-out: 215,-245 275,-245 275,-215 215,-215

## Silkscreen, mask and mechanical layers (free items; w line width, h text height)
Top Overlay:
  text "5V" at 10,-105 h50 r90
  text "CLK" at 10,-225 h50 r90
  text "DIO" at 10,-325 h50 r90
  text "GND" at 10,-440 h50 r90
  text "20240509" at -45,-500 h70 r90
  text "LKS_EVB_MCUAT039_V6.1" at -95,-655 h70 r90
  text "VCC" at 585,-1460 h70
  text "GND" at 1040,-1465 h70
  text "OUT" at -70,-1495 h50
  text "GND" at 30,-1495 h50
  text "GND" at 145,-1495 h50
  text "IN" at 270,-1495 h50
  text "LIN" at -60,-1535 h50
